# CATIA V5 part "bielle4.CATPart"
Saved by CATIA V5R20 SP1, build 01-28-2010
Part number: bielle4
Bounding box of the stored display mesh (mm): x -232 to -128, y 0 to 10, z 97.974 to 111.801
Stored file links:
  E:\EDELI\gcausse\Edeli_2012_184_gcausse\bielle4.CATPart
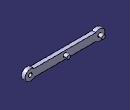
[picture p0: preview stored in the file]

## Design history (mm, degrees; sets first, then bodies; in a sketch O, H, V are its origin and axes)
Body1 (main body)
  Sketch1 on zx-plane, origin (0, 0, 0), H (-1, 0, 0), V (0, 0, 1)
    line L1 (220.101, 109.899) -> (139.899, 109.899)
    line L2 (220, 100) -> (140, 100)
    arc A1 centre (225, 104.899) radius 7 from (220.101, 109.899) to (220, 100) cw
    point P5 (225, 104.899)
    point P6 (230, 100)
    arc A2 centre (135, 104.899) radius 7 from (139.899, 109.899) to (140, 100) ccw
    point P7 (135, 104.899)
    point P8 (130, 100)
    circle A3 centre (135, 104.899) radius 2.5
    radius A2 = 7
    radius A1 = 7
    distance P5 L1 = 5
    distance P7 L1 = 5
    distance P5 P7 = 90
    radius A3 = 2.5
    horizontal: L1 H, L2 H
    coincidence: A1 P6, P6 L2, A2 P8, P8 L2
  Pad1: profile Sketch1, direction (0, 1, 0), length 5
  Sketch2 on end face of Pad1, origin (0, 5, 0), H (-1, 0, 0), V (0, 0, 1)
    circle A1 centre (225, 104.899) radius 2.5
    reference projected arc E1 centre (225, 104.899) radius 7 from (220, 100) to (220.101, 109.899) ccw from edge [face of Pad1 from Sketch1.A1 | end face of Pad1]
    reference projected arc E2 centre (225, 104.899) radius 7 from (220, 100) to (220.101, 109.899) ccw from edge [face of Pad1 from Sketch1.A1 | end face of Pad1]
    radius A1 = 2.5
    radius E2 = 7 (reference)
    concentricity: A1 E1
  Pad2: profile Sketch2, direction (0, 1, 0), length 5
  DatumSurface1
  DatumSurface2
  Sketch3 on end face of Pad1, origin (0, 5, 0), H (-1, 0, 0), V (0, 0, 1)
    circle A1 centre (180, 104.9495) radius 2.5
    point P1 (180, 104.9495)
    reference projected line E1 (220.101, 109.899) -> (139.899, 109.899) from edge [face of Pad1 from Sketch1.L1 | end face of Pad1]
    reference projected line E2 (140, 100) -> (220, 100) from edge [face of Pad1 from Sketch1.L2 | end face of Pad1]
    reference intersected circle E3 centre (135, 104.899) radius 2.5 from face of DatumSurface1
    radius A1 = 2.5
    distance P1 E3 = 47.5
    equidistance: E1 E2 P1
  Pad3: profile Sketch3, direction (0, 1, 0), length 5
  DatumCurve1 to DatumCurve3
